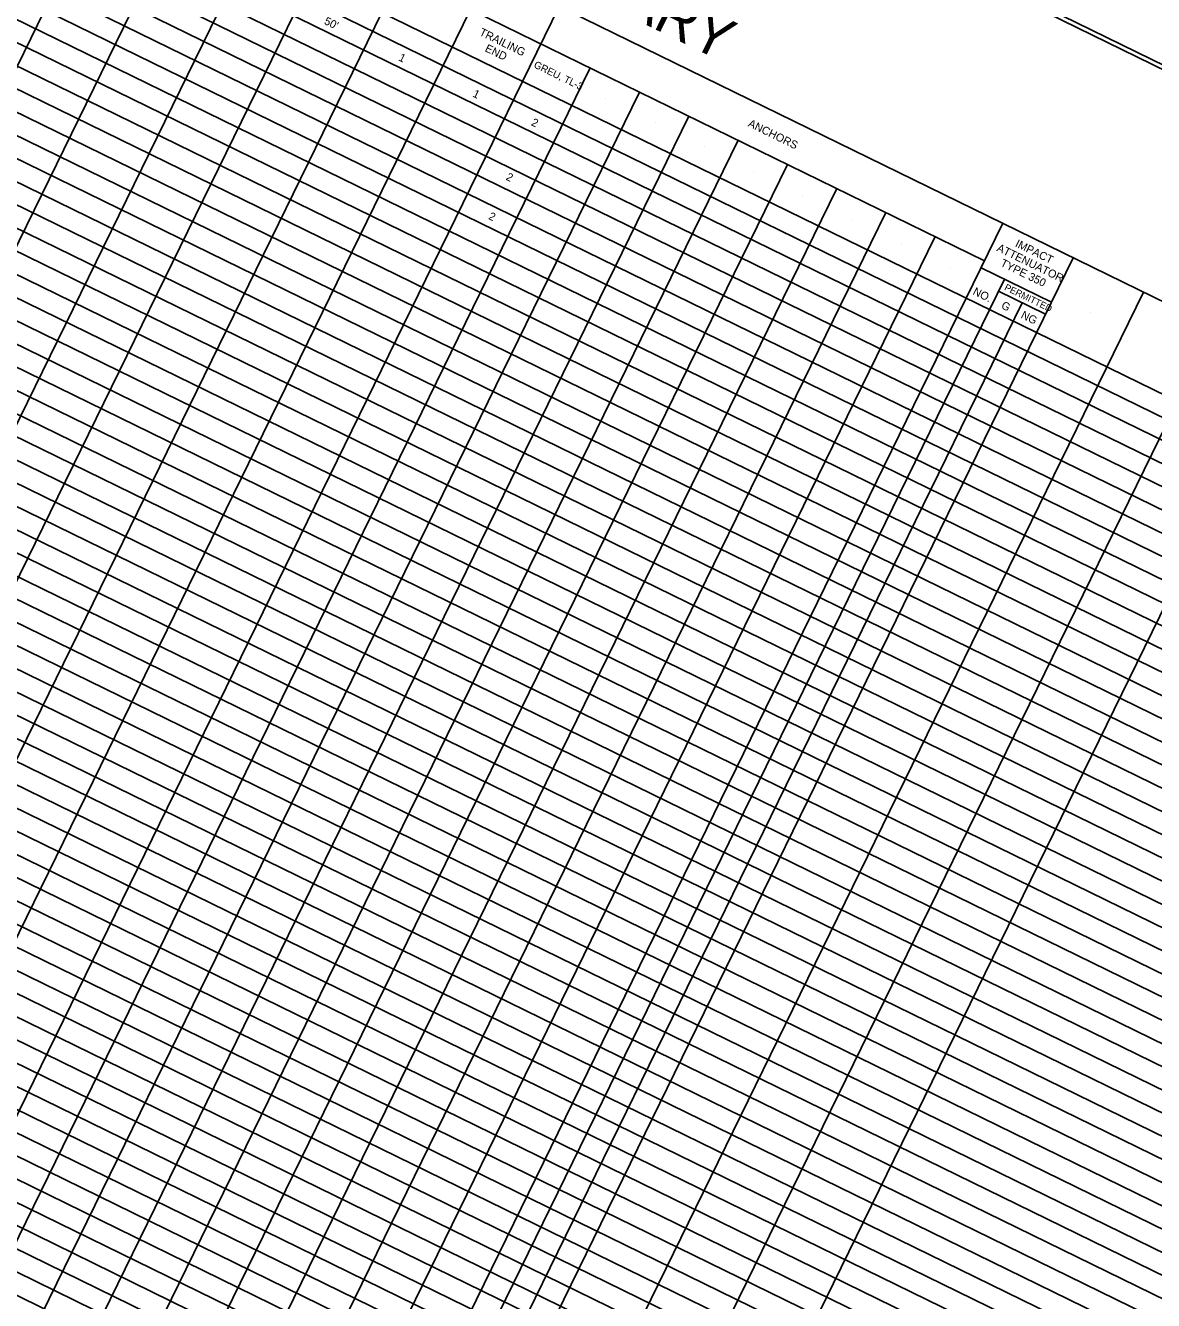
# Model space of a CAD drawing. Extents: x 1524707 to 1527186, y 631886 to 634602.
# Drawn here: x 1526168 to 1526844, y 633261 to 634025 of the extents above; entities that cross this region are included whole.
import ezdxf

# ---------------------------------------------------------------- set-up
doc = ezdxf.new("R2010")
doc.units = 0
doc.layers.add('Sheet Plot Border Inside CELL', color=7, linetype='Continuous')
doc.layers.add('Sheet Summary Guardrail CELL', color=7, linetype='Continuous')

msp = doc.modelspace()

# ---------------------------------------------------------------- linework, layer by layer
at = {"layer": 'Sheet Plot Border Inside CELL'}
msp.add_lwpolyline([(1525211.97, 633628.34), (1526709.01, 632896.16), (1527172.57, 633843.98), (1525675.52, 634576.15)], close=True, dxfattribs=at)
at = {"layer": 'Sheet Summary Guardrail CELL'}
for p, q in [((1525757.82, 634393.91), (1527105.3, 633734.89)), ((1525735.86, 634348.99), (1527083.33, 633689.97)), ((1525730.37, 634337.76), (1527077.84, 633678.74)), ((1525724.87, 634326.54), (1527072.35, 633667.51)), ((1525719.38, 634315.31), (1527066.86, 633656.29)), ((1525713.89, 634304.08), (1527061.37, 633645.06)), ((1525708.4, 634292.85), (1527055.87, 633633.83)), ((1525702.91, 634281.62), (1527050.38, 633622.6)), ((1525697.41, 634270.39), (1527044.89, 633611.37)), ((1525691.92, 634259.16), (1527039.4, 633600.14)), ((1525686.43, 634247.93), (1527033.91, 633588.91)), ((1525680.94, 634236.7), (1527028.41, 633577.68)), ((1525675.45, 634225.48), (1527022.92, 633566.45)), ((1525669.96, 634214.25), (1527017.43, 633555.22)), ((1525664.46, 634203.02), (1527011.94, 633544)), ((1525658.97, 634191.79), (1527006.45, 633532.77)), ((1525653.48, 634180.56), (1527000.96, 633521.54)), ((1525647.99, 634169.33), (1526995.46, 633510.31)), ((1525642.5, 634158.1), (1526989.97, 633499.08)), ((1526239.77, 634158.2), (1525833.38, 633327.26)), ((1525637, 634146.87), (1526984.48, 633487.85)), ((1525631.51, 634135.64), (1526978.99, 633476.62)), ((1526281.99, 634137.55), (1525875.6, 633306.61)), ((1525626.02, 634124.41), (1526973.5, 633465.39)), ((1526324.21, 634116.9), (1525917.82, 633285.96)), ((1525620.53, 634113.19), (1526968, 633454.16)), ((1525615.04, 634101.96), (1526962.51, 633442.93)), ((1526742.98, 633884.26), (1526313.23, 634094.44)), ((1525609.54, 634090.73), (1526957.02, 633431.71)), ((1525604.05, 634079.5), (1526951.53, 633420.48)), ((1526403.54, 634078.11), (1525997.14, 633247.16)), ((1526350.33, 634076.3), (1525954.92, 633267.81)), ((1525598.56, 634068.27), (1526946.04, 633409.25)), ((1525593.07, 634057.04), (1526940.54, 633398.02)), ((1525587.58, 634045.81), (1526935.05, 633386.79)), ((1525582.09, 634034.58), (1526929.56, 633375.56)), ((1526434.77, 634035), (1526039.36, 633226.51)), ((1526487.98, 634036.81), (1526081.58, 633205.86)), ((1525576.59, 634023.35), (1526924.07, 633364.33)), ((1525571.1, 634012.12), (1526918.58, 633353.1)), ((1525565.61, 634000.9), (1526913.09, 633341.87)), ((1526506.55, 633999.9), (1526111.13, 633191.41)), ((1526486.28, 633995.89), (1526486.28, 633995.89)), ((1525560.12, 633989.67), (1526907.59, 633330.65)), ((1526536.1, 633985.44), (1526140.69, 633176.96)), ((1526515.83, 633981.44), (1526515.83, 633981.44)), ((1525554.63, 633978.44), (1526902.1, 633319.42)), ((1525549.13, 633967.21), (1526896.61, 633308.19)), ((1526565.66, 633970.99), (1526170.24, 633162.5)), ((1526545.39, 633966.98), (1526545.39, 633966.98)), ((1525543.64, 633955.98), (1526891.12, 633296.96)), ((1526595.21, 633956.53), (1526199.8, 633148.05)), ((1526574.94, 633952.53), (1526574.94, 633952.53)), ((1525538.15, 633944.75), (1526885.63, 633285.73)), ((1526624.77, 633942.08), (1526229.35, 633133.59)), ((1525532.66, 633933.52), (1526880.13, 633274.5)), ((1526604.5, 633938.08), (1526604.5, 633938.08)), ((1526654.32, 633927.62), (1526258.91, 633119.14)), ((1525527.17, 633922.29), (1526874.64, 633263.27)), ((1526634.05, 633923.62), (1526634.05, 633923.62)), ((1525521.68, 633911.06), (1526869.15, 633252.04)), ((1526683.88, 633913.17), (1526288.46, 633104.68)), ((1526753.97, 633906.72), (1526347.57, 633075.77)), ((1526663.61, 633909.17), (1526663.61, 633909.17)), ((1525516.18, 633899.84), (1526863.66, 633240.81)), ((1526713.43, 633898.71), (1526318.02, 633090.23)), ((1526693.16, 633894.71), (1526693.16, 633894.71)), ((1525510.69, 633888.61), (1526858.17, 633229.58)), ((1526796.19, 633886.07), (1526389.79, 633055.12)), ((1526722.72, 633880.26), (1526722.72, 633880.26)), ((1526740.9, 633879.99), (1526783.12, 633859.34)), ((1525505.2, 633877.38), (1526852.68, 633218.36)), ((1526754.96, 633873.12), (1526361.63, 633068.9)), ((1525499.71, 633866.15), (1526847.18, 633207.13)), ((1526838.41, 633865.42), (1526432.01, 633034.47)), ((1526751.44, 633865.93), (1526779.6, 633852.16)), ((1526777.32, 633867.74), (1526777.32, 633867.74)), ((1526765.5, 633859.05), (1526375.69, 633062.02)), ((1525494.22, 633854.92), (1526841.69, 633195.9)), ((1526806.32, 633853.28), (1526806.32, 633853.28)), ((1525488.72, 633843.69), (1526836.2, 633184.67)), ((1526880.63, 633844.77), (1526474.23, 633013.83)), ((1525483.23, 633832.46), (1526830.71, 633173.44)), ((1525477.74, 633821.23), (1526825.22, 633162.21)), ((1526922.85, 633824.12), (1526516.46, 632993.18)), ((1525472.25, 633810), (1526819.72, 633150.98)), ((1525466.76, 633798.77), (1526814.23, 633139.75)), ((1525461.27, 633787.55), (1526808.74, 633128.52)), ((1525455.77, 633776.32), (1526803.25, 633117.29)), ((1525450.28, 633765.09), (1526797.76, 633106.07)), ((1525444.79, 633753.86), (1526792.27, 633094.84)), ((1525439.3, 633742.63), (1526786.77, 633083.61)), ((1525433.81, 633731.4), (1526781.28, 633072.38)), ((1525428.31, 633720.17), (1526775.79, 633061.15)), ((1525422.82, 633708.94), (1526770.3, 633049.92)), ((1525417.33, 633697.71), (1526764.81, 633038.69)), ((1525411.84, 633686.48), (1526759.31, 633027.46)), ((1525406.35, 633675.26), (1526753.82, 633016.23)), ((1525400.85, 633664.03), (1526748.33, 633005.01)), ((1525395.36, 633652.8), (1526742.84, 632993.78)), ((1525389.87, 633641.57), (1526737.35, 632982.55))]:
    msp.add_line(p, q, dxfattribs=at)
msp.add_lwpolyline([(1527160.22, 633847.18), (1525812.74, 634506.2), (1525351.43, 633562.97), (1526698.9, 632903.94)], close=True, dxfattribs=at)

# ---------------------------------------------------------------- texts
for s, height, p in [('GUARDRAIL SUMMARY', 24.9999, (1526247.95, 634168.56)), ("50'", 4.8, (1526346.51, 634026.48)), ('TRAILING', 4.8, (1526439.58, 634019.79)), ('END', 4.8, (1526442.97, 634010.12)), ('1', 4.8, (1526391.19, 634004.62)), ('GREU, TL-3', 4.332, (1526472.27, 634000.41)), ('1', 4.8, (1526435.59, 633982.91)), ('2', 4.8, (1526470.73, 633965.72)), ('ANCHORS', 4.8, (1526600.73, 633965.08)), ('2', 4.8, (1526455.58, 633933.02)), ('2', 4.8, (1526445.07, 633909.42)), ('IMPACT', 4.8, (1526760.95, 633892.96)), ('ATTENUATOR', 4.8, (1526749.88, 633890.36)), ('TYPE 350', 4.8, (1526752.06, 633881.28)), ('NO.', 4.8, (1526735.57, 633864.26)), ('PERMITTED', 4, (1526754.55, 633866.97)), ('G', 4.8, (1526752.56, 633855.92)), ('NG', 4.8, (1526764.42, 633850.12))]:
    msp.add_text(s, height=height, rotation=333.93772, dxfattribs=at).set_placement(p)

doc.saveas('drawing.dxf')
